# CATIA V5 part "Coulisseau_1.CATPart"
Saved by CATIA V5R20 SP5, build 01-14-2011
Part number: Coulisseau-1
Bounding box of the stored display mesh (mm): x -36.008 to -20.352, y -39.271 to -22.147, z 3 to 12
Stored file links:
  D:\thinkmotion-MPB\Dropbox\IAO_2011\MMS_GR3\IAO_2011_1523_mkessler\mkessler\mkessler_IAO\mkessler_INIT\Coulisseau_1.CATPart
  C:\Users\MARLENE\Documents\IFMA\S3\IAO\Copie de CAO\Assemblage_final.CATProduct
  D:\thinkmotion-MPB\Dropbox\IAO_2011\MMS_GR3\IAO_2011_1523_mkessler\mkessler\mkessler_IAO\mkessler_INIT\Squelette_coulisseau_1.CATPart
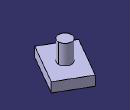
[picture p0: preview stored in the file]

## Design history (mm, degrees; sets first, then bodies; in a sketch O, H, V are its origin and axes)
External parameters (linked from other documents)
  External.Longueur_coulisseau_1 = 14 mm
  External.Largeur_coulisseau_1 = 10 mm
Set1
  Plane1: linked copy from another document
  Line1: linked copy from another document
  Line2: linked copy from another document
  Point1: linked copy from another document
Body1 (main body)
  Sketch1 on Plane1, origin (0, 0, 3), H (1, 0, 0), V (0, 1, 0)
    line L1 (-36.0083, -34.2752) -> (-29.0146, -22.1472)
    line L2 (-36.0083, -34.2752) -> (-27.3454, -39.2707)
    line L3 (-27.3454, -39.2707) -> (-20.3517, -27.1428)
    line L4 (-20.3517, -27.1428) -> (-29.0146, -22.1472)
    reference projected line E1 (-40.4698, -42.0121) -> (-6.5003, 16.8953) from Line1
    reference projected line E2 (-20.3517, -27.1428) -> (-29.0146, -22.1472) from Line2
    length L4 = 10 {= External.Largeur_coulisseau_1}
    length L3 = 14 {= External.Longueur_coulisseau_1}
    length L2 = 10 {= Sketch1.length(L4)}
    length L1 = 14 {= Sketch1.length(L3)}
    perpendicularity: L2 L1
    parallelism: L3 L1
    coincidence: L1 E1, L4 E2
  Pad1: profile Sketch1, direction (0, 0, 1), length 3
  Sketch2 on end face of Pad1, origin (0, 0, 6), H (1, 0, 0), V (0, 1, 0)
    circle A1 centre (-28.18, -30.709) radius 2
    reference projected point E1 (-28.18, -30.709) from Point1
    radius A1 = 2
    concentricity: A1 E1
  Pad2: profile Sketch2, direction (0, 0, 1), length 6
